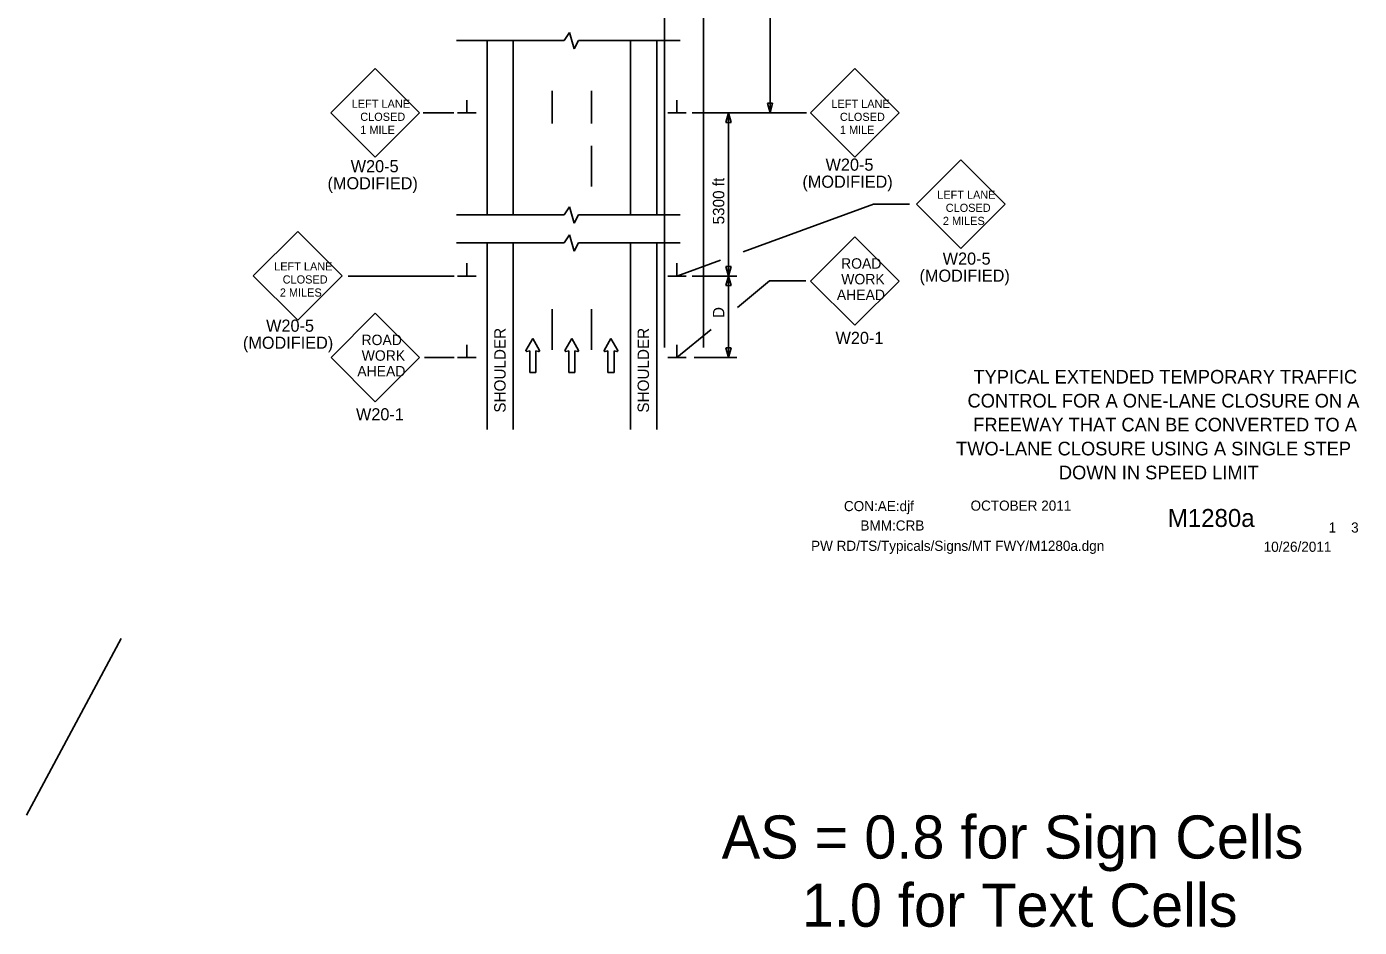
# Model space of a CAD drawing. Extents: x 16590 to 19508, y 5703 to 6974.
# Drawn here: x 16590 to 17407, y 5703 to 6255 of the extents above; entities that cross this region are included whole.
import ezdxf

# ---------------------------------------------------------------- set-up
doc = ezdxf.new("R2010")
doc.units = 0
for name, color, linetype in [('ALI_LEGAL_EX', 7, 'Continuous'), ('BORDER', 7, 'Continuous'), ('BORDER_SIGNAL_WO', 7, 'Continuous'), ('MT_SCRATCH_LEVEL_E', 7, 'Continuous'), ('PAVT_EDGE_EX', 7, 'Continuous'), ('TRAFFIC_SIGNS_PR', 7, 'Continuous'), ('TYPICAL_TEXT_DIMEN_PR', 7, 'Continuous')]:
    doc.layers.add(name, color=color, linetype=linetype)

msp = doc.modelspace()

# ---------------------------------------------------------------- linework, layer by layer
at = {"layer": 'ALI_LEGAL_EX'}
for p, q in [((16980.68, 6974.12), (16980.68, 6155.98)), ((17004.68, 6974.12), (17004.68, 6155.98)), ((16980.68, 6922.21), (16980.68, 6058.3)), ((17004.68, 6922.21), (17004.68, 6058.3))]:
    msp.add_line(p, q, dxfattribs=at)
for points in [[(16911.96, 6215.64), (16911.96, 6195.69)], [(16935.96, 6215.64), (16935.96, 6195.69)], [(16935.96, 6156.97), (16935.96, 6181.97)], [(16911.96, 6081.97), (16911.96, 6056.97)], [(16935.96, 6081.97), (16935.96, 6056.97)]]:
    msp.add_lwpolyline(points, dxfattribs=at)
at = {"layer": 'MT_SCRATCH_LEVEL_E'}
for p, q in [((16899.96, 6063.87), (16895.85, 6056.63)), ((16904.1, 6056.63), (16899.96, 6063.87)), ((16923.86, 6063.87), (16919.75, 6056.63)), ((16928.01, 6056.63), (16923.86, 6063.87)), ((16947.91, 6063.87), (16943.8, 6056.63)), ((16952.06, 6056.63), (16947.91, 6063.87)), ((16896.33, 6055.95), (16898.1, 6056.26)), ((16898.1, 6056.26), (16898.1, 6043.01)), ((16901.85, 6043.01), (16901.85, 6056.26)), ((16901.85, 6056.26), (16903.62, 6055.95)), ((16920.23, 6055.95), (16922.01, 6056.26)), ((16922.01, 6056.26), (16922.01, 6043.01)), ((16925.75, 6043.01), (16925.75, 6056.26)), ((16925.75, 6056.26), (16927.53, 6055.95)), ((16944.28, 6055.95), (16946.06, 6056.26)), ((16946.06, 6056.26), (16946.06, 6043.01)), ((16949.8, 6043.01), (16949.8, 6056.26)), ((16949.8, 6056.26), (16951.58, 6055.95)), ((16898.1, 6043.01), (16901.85, 6043.01)), ((16922.01, 6043.01), (16925.75, 6043.01)), ((16946.06, 6043.01), (16949.8, 6043.01))]:
    msp.add_line(p, q, dxfattribs=at)
for centre, start, end in [((16896.25, 6056.41), 150.42484, 279.96381), ((16903.69, 6056.41), 260.03619, 29.77312), ((16920.16, 6056.41), 150.42484, 279.96381), ((16927.6, 6056.41), 260.03619, 29.77312), ((16944.21, 6056.41), 150.42484, 279.96381), ((16951.65, 6056.41), 260.03619, 29.77312)]:
    msp.add_arc(centre, 0.463, start, end, dxfattribs=at)
at = {"layer": 'PAVT_EDGE_EX'}
for p, q in [((16871.96, 6246.66), (16871.96, 6216.94)), ((16887.96, 6246.66), (16887.96, 6216.94)), ((16959.96, 6246.66), (16959.96, 6216.94)), ((16975.96, 6246.66), (16975.96, 6216.94)), ((16871.96, 6216.94), (16871.96, 6139.77)), ((16887.96, 6216.94), (16887.96, 6139.78)), ((16959.96, 6216.94), (16959.96, 6139.78)), ((16975.96, 6216.94), (16975.96, 6139.78)), ((16871.96, 6122.63), (16871.96, 6008.06)), ((16887.96, 6122.63), (16887.96, 6008.06)), ((16959.96, 6122.63), (16959.96, 6008.06)), ((16975.96, 6122.63), (16975.96, 6008.06))]:
    msp.add_line(p, q, dxfattribs=at)
at = {"layer": 'TRAFFIC_SIGNS_PR'}
for p, q in [((16803.47, 6229.38), (16776.29, 6202.19)), ((16830.66, 6202.19), (16803.47, 6229.38)), ((17097.4, 6229.34), (17070.22, 6202.16)), ((17124.59, 6202.16), (17097.4, 6229.34)), ((16776.29, 6202.19), (16803.47, 6175)), ((16803.47, 6175), (16830.66, 6202.19)), ((17070.22, 6202.16), (17097.4, 6174.97)), ((17097.4, 6174.97), (17124.59, 6202.16)), ((17162.26, 6173.34), (17135.07, 6146.16)), ((17189.44, 6146.16), (17162.26, 6173.34)), ((17135.07, 6146.16), (17162.26, 6118.97)), ((17162.26, 6118.97), (17189.44, 6146.16)), ((16755.92, 6129.44), (16728.73, 6102.25)), ((16783.11, 6102.25), (16755.92, 6129.44)), ((17097.4, 6126.29), (17070.25, 6099.14)), ((17124.56, 6099.14), (17097.4, 6126.29)), ((16728.73, 6102.25), (16755.92, 6075.06)), ((16755.92, 6075.06), (16783.11, 6102.25)), ((17070.25, 6099.14), (17097.4, 6071.99)), ((17097.4, 6071.99), (17124.56, 6099.14)), ((16803.51, 6079.45), (16776.36, 6052.3)), ((16830.67, 6052.3), (16803.51, 6079.45)), ((16776.36, 6052.3), (16803.51, 6025.15)), ((16803.51, 6025.15), (16830.67, 6052.3))]:
    msp.add_line(p, q, dxfattribs=at)
at = {"layer": 'TYPICAL_TEXT_DIMEN_PR'}
for p, q in [((17045.39, 6555.41), (17045.39, 6202.2)), ((16922.56, 6251.46), (16919.31, 6246.66)), ((16925.3, 6241.52), (16922.56, 6251.46)), ((16919.31, 6246.66), (16853.36, 6246.66)), ((16928.05, 6246.66), (16925.3, 6241.52)), ((16990.38, 6246.66), (16928.05, 6246.66)), ((16859.58, 6202.2), (16859.58, 6209.99)), ((16988.33, 6202.2), (16988.33, 6209.99)), ((17045.39, 6202.2), (17043.82, 6208.07)), ((17043.82, 6208.07), (17045.39, 6208.07)), ((17045.39, 6208.07), (17046.97, 6208.07)), ((17046.97, 6208.07), (17045.39, 6202.2)), ((16851.6, 6202.2), (16832.82, 6202.2)), ((16853.96, 6202.2), (16865.21, 6202.2)), ((16993.96, 6202.2), (16982.71, 6202.2)), ((17067.79, 6202.2), (16997.63, 6202.2)), ((17018.39, 6196.34), (17019.96, 6202.2)), ((17019.96, 6202.2), (17019.96, 6102.2)), ((17019.96, 6202.2), (17021.53, 6196.34)), ((17019.96, 6196.34), (17018.39, 6196.34)), ((17021.53, 6196.34), (17019.96, 6196.34)), ((16922.56, 6144.57), (16919.31, 6139.77)), ((16925.3, 6134.63), (16922.56, 6144.57)), ((17028.84, 6116.99), (17108.73, 6146.16)), ((17108.73, 6146.16), (17130.92, 6146.16)), ((16919.31, 6139.77), (16853.36, 6139.77)), ((16928.05, 6139.77), (16925.3, 6134.63)), ((16990.38, 6139.77), (16928.05, 6139.77)), ((16922.56, 6127.43), (16919.31, 6122.63)), ((16925.3, 6117.49), (16922.56, 6127.43)), ((16919.31, 6122.63), (16853.36, 6122.63)), ((16928.05, 6122.63), (16925.3, 6117.49)), ((16990.38, 6122.63), (16928.05, 6122.63)), ((16859.58, 6102.2), (16859.58, 6109.99)), ((16988.33, 6102.2), (17015.07, 6111.97)), ((16988.33, 6102.2), (16988.33, 6109.99)), ((16851.75, 6102.2), (16786.8, 6102.2)), ((16853.96, 6102.2), (16865.21, 6102.2)), ((16993.96, 6102.2), (16982.71, 6102.2)), ((17024.96, 6102.2), (16997.63, 6102.2)), ((17019.96, 6102.2), (17018.39, 6108.07)), ((17018.39, 6108.07), (17019.96, 6108.07)), ((17018.39, 6096.34), (17019.96, 6102.2)), ((17019.96, 6108.07), (17021.53, 6108.07)), ((17021.53, 6108.07), (17019.96, 6102.2)), ((17019.96, 6102.2), (17019.96, 6052.2)), ((17019.96, 6102.2), (17021.53, 6096.34)), ((17019.96, 6096.34), (17018.39, 6096.34)), ((17021.53, 6096.34), (17019.96, 6096.34)), ((17045.1, 6099.18), (17025.48, 6082.94)), ((17045.1, 6099.18), (17067.29, 6099.18)), ((17009.23, 6069.5), (16988.33, 6052.2)), ((16833.64, 6052.2), (16851.8, 6052.2)), ((16853.96, 6052.2), (16865.21, 6052.2)), ((16859.58, 6052.2), (16859.58, 6059.99)), ((16993.96, 6052.2), (16982.71, 6052.2)), ((16988.33, 6052.2), (16988.33, 6059.99)), ((17024.96, 6052.2), (16998.96, 6052.2)), ((17019.96, 6052.2), (17018.39, 6058.07)), ((17018.39, 6058.07), (17019.96, 6058.07)), ((17019.96, 6058.07), (17021.53, 6058.07)), ((17021.53, 6058.07), (17019.96, 6052.2)), ((16647.75, 5880), (16589.83, 5771.74))]:
    msp.add_line(p, q, dxfattribs=at)

# ---------------------------------------------------------------- texts
at = {"layer": 'BORDER'}
for s, p in [('TYPICAL EXTENDED TEMPORARY TRAFFIC', (17170.06, 6036.26)), ('CONTROL FOR A ONE-LANE CLOSURE ON A', (17166.43, 6021.59)), ('FREEWAY THAT CAN BE CONVERTED TO A', (17169.93, 6006.91)), ('TWO-LANE CLOSURE USING A SINGLE STEP ', (17159.43, 5992.23)), ('DOWN IN SPEED LIMIT', (17222.43, 5977.56))]:
    msp.add_text(s, height=8.3734, dxfattribs=at).set_placement(p)
at = {"layer": 'BORDER_SIGNAL_WO'}
for s, height, p in [('CON:AE:djf  ', 6.2, (17090.69, 5958.06)), ('    OCTOBER 2011    ', 6.2, (17159.08, 5958.34)), ('    M1280a   ', 11, (17272.86, 5948.38)), ('BMM:CRB   ', 6.2, (17100.81, 5946.17)), (' 1    3 ', 6.2, (17385.4, 5944.93)), ('PW RD/TS/Typicals/Signs/MT FWY/M1280a.dgn      ', 6.2, (17070.55, 5933.71)), ('10/26/2011    ', 6.2, (17347.93, 5933.13)), ('AS = 0.8 for Sign Cells', 26.4241, (17015.79, 5745.09)), ('     1.0 for Text Cells', 26.4241, (17015.79, 5703.3))]:
    msp.add_text(s, height=height, dxfattribs=at).set_placement(p)
at = {"layer": 'TRAFFIC_SIGNS_PR'}
for s, height, p in [('LEFT LANE', 5.006, (16789.08, 6205.31)), ('LEFT LANE', 5.006, (17083.02, 6205.28)), ('CLOSED', 5.006, (16794.29, 6197.3)), ('CLOSED', 5.006, (17088.23, 6197.27)), ('1 MILE', 5.006, (16794.29, 6189.3)), ('1 MILE', 5.006, (17088.22, 6189.27)), ('W20-5', 7.449, (16788.43, 6165.79)), ('W20-5', 7.449, (17079.45, 6166.75)), ('(MODIFIED)', 7.449, (16774.23, 6155.34)), ('(MODIFIED)', 7.449, (17065.25, 6156.3)), ('LEFT LANE', 5.006, (17147.87, 6149.51)), ('CLOSED', 5.006, (17153.08, 6141.5)), ('2 MILES', 5.006, (17151.33, 6133.49)), ('LEFT LANE', 5.006, (16741.53, 6105.6)), ('ROAD', 6.4, (17088.94, 6106.68)), ('W20-5', 7.449, (17151.23, 6109.14)), ('CLOSED', 5.006, (16746.74, 6097.59)), ('WORK', 6.4, (17089.05, 6097.08)), ('(MODIFIED)', 7.449, (17137.03, 6098.69)), ('2 MILES', 5.006, (16744.99, 6089.58)), ('AHEAD', 6.4, (17086.36, 6087.48)), ('W20-5', 7.449, (16736.58, 6068.03)), ('(MODIFIED)', 7.449, (16722.38, 6057.58)), ('ROAD', 6.4, (16795.05, 6059.84)), ('W20-1', 7.44, (17085.57, 6060.55)), ('WORK', 6.4, (16795.16, 6050.24)), ('AHEAD', 6.4, (16792.47, 6040.64)), ('W20-1', 7.44, (16791.68, 6013.71))]:
    msp.add_text(s, height=height, dxfattribs=at).set_placement(p)
at = {"layer": 'TYPICAL_TEXT_DIMEN_PR'}
for s, p in [('5300 ft', (17017.4, 6133.81)), ('D', (17017.4, 6076.42)), ('SHOULDER', (16883.38, 6018.42)), ('SHOULDER', (16971.24, 6018.42))]:
    msp.add_text(s, height=7, rotation=90, dxfattribs=at).set_placement(p)

doc.saveas('drawing.dxf')
